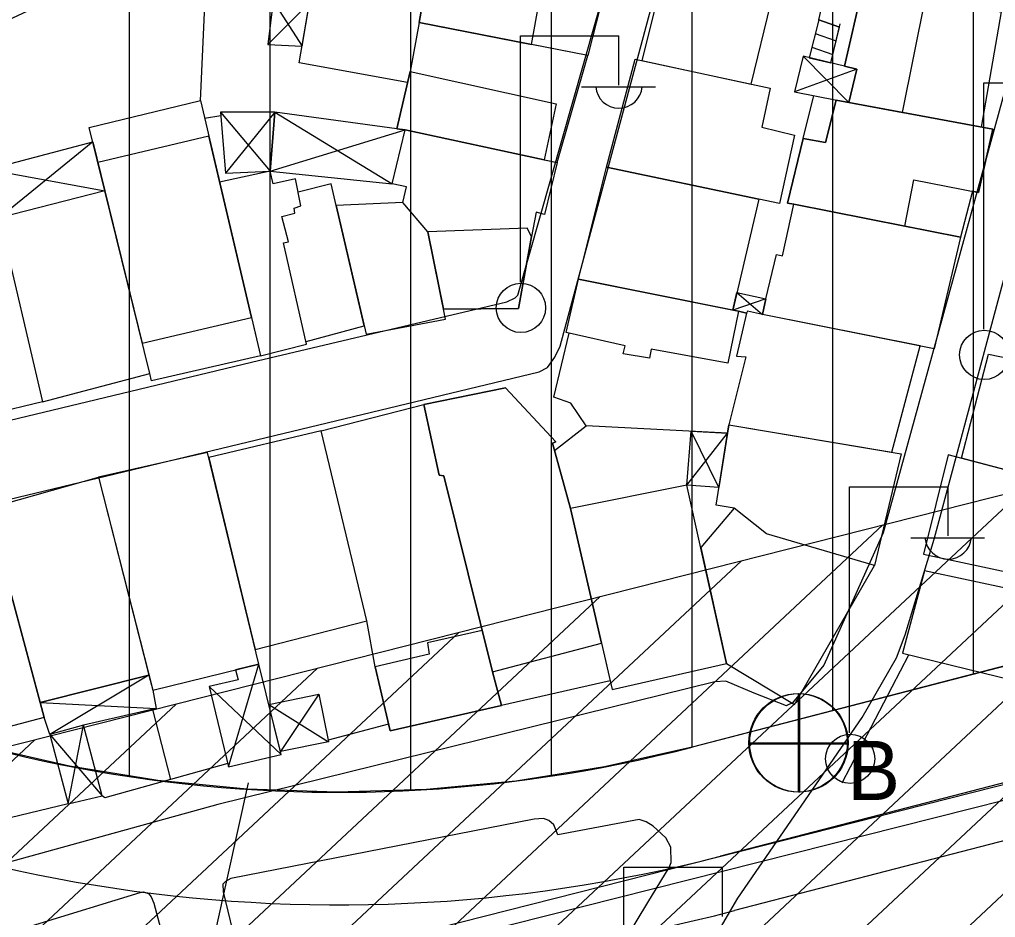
# Model space of a CAD drawing. Extents: x 417997 to 421451, y 4451742 to 4455216.
# Drawn here: x 419463 to 419532.4, y 4452595.7 to 4452659.5 of the extents above; entities that cross this region are included whole.
import ezdxf

# ---------------------------------------------------------------- set-up
doc = ezdxf.new("R2010")
doc.units = 0
for name, color, linetype in [('ADAKENARI', 7, 'Continuous'), ('B_Merdiven', 7, 'Continuous'), ('B_Mesken', 7, 'Continuous'), ('B_Sundurma', 7, 'Continuous'), ('B_Teras', 7, 'Continuous'), ('Hat_ENH', 7, 'Continuous'), ('KALDIRIM', 7, 'Continuous'), ('PL_KON_MEV_350', 7, 'Continuous'), ('S_Elektrik_Diregi', 7, 'Continuous'), ('S_Rogar_Kapagi', 7, 'Continuous'), ('S_Rogar_Kapagi_Buski', 7, 'Continuous'), ('S_Serare', 7, 'Continuous'), ('Sinir_Duvar_tek_tarafa_ait', 7, 'Continuous'), ('Sinir_Ist_Duvari', 7, 'Continuous'), ('TA_ENH_154', 7, 'Continuous'), ('TA_ENH_KORUMA', 7, 'Continuous'), ('TA_ENH_TARAMA', 7, 'Continuous'), ('TR_ORTAYOGUNKONUT', 7, 'Continuous'), ('Yol_Sose', 7, 'Continuous')]:
    doc.layers.add(name, color=color, linetype=linetype)

msp = doc.modelspace()

# ---------------------------------------------------------------- linework, layer by layer
at = {"layer": 'ADAKENARI'}
msp.add_line((419536.19, 4452614.337), (419510.852, 4452607.764), dxfattribs=at)
msp.add_line((419536.19, 4452614.337), (419510.852, 4452607.764), dxfattribs=at)
msp.add_arc((419485.743, 4452704.56), 100, 237.03266, 284.5422, dxfattribs=at)
msp.add_arc((419485.743, 4452704.56), 100, 237.03266, 284.5422, dxfattribs=at)
at = {"layer": 'B_Merdiven'}
for p, q in [((419519.85, 4452659.45), (419521.322, 4452658.932)), ((419519.608, 4452658.475), (419521.086, 4452657.955)), ((419519.366, 4452657.501), (419520.85, 4452656.978))]:
    msp.add_line(p, q, dxfattribs=at)
msp.add_lwpolyline([(419519.85, 4452659.45), (419519.178, 4452656.746), (419520.705, 4452656.377), (419521.322, 4452658.932)], close=True, dxfattribs=at)
at = {"layer": 'B_Mesken'}
for points in [[(419490.633, 4452654.997), (419482.933, 4452656.379), (419483.653, 4452660.642), (419484.79, 4452668.632), (419484.86, 4452669.356), (419492.964, 4452667.865), (419491.446, 4452659.243), (419490.814, 4452655.782)], [(419500.954, 4452666.062), (419505.551, 4452665.187), (419503.447, 4452656.919), (419499.436, 4452657.696), (419491.446, 4452659.243), (419492.99, 4452668.018), (419501.029, 4452666.476)], [(419515.043, 4452654.88), (419516.45, 4452660.606), (419516.928, 4452660.514), (419517.437, 4452662.9), (419509.317, 4452664.699), (419507.285, 4452656.55)], [(419527.417, 4452660.892), (419532.809, 4452660.011), (419531.401, 4452651.824), (419525.8, 4452652.867), (419521.987, 4452653.566), (419522.563, 4452655.929), (419521.677, 4452656.143), (419522.937, 4452661.614)], [(419501.269, 4452649.295), (419503.447, 4452656.919), (419491.446, 4452659.243), (419490.814, 4452655.782), (419489.872, 4452651.709), (419490.461, 4452651.617), (419500.337, 4452649.495)], [(419504.774, 4452648.981), (419506.795, 4452656.656), (419516.403, 4452654.587), (419515.804, 4452651.824), (419518.138, 4452651.251), (419517.056, 4452646.382), (419515.583, 4452646.704)], [(419469.113, 4452647.302), (419467.996, 4452651.783), (419475.9, 4452653.704), (419480.185, 4452635.576), (419472.44, 4452633.791), (419472.302, 4452634.312)], [(419530.792, 4452647.264), (419529.926, 4452643.992), (419525.962, 4452644.783), (419518.093, 4452646.353), (419517.635, 4452646.422), (419518.749, 4452650.999), (419520.34, 4452650.736), (419521.088, 4452653.744), (419532.223, 4452651.672), (419531.21, 4452647.184)], [(419490.285, 4452646.473), (419490.561, 4452647.583), (419489.541, 4452647.79), (419490.461, 4452651.617), (419501.269, 4452649.295), (419500.35, 4452645.604), (419499.761, 4452645.787), (419499.44, 4452644.037), (419498.516, 4452638.941), (419493.187, 4452638.889), (419492.066, 4452644.387)], [(419464.674, 4452632.302), (419443.489, 4452627.183), (419442.095, 4452627.905), (419454.05, 4452647.229), (419459.141, 4452648.35), (419459.79, 4452645.497), (419461.467, 4452645.89), (419461.605, 4452645.371)], [(419483.41, 4452636.588), (419487.555, 4452637.699), (419485.554, 4452646.239), (419485.197, 4452647.781), (419482.852, 4452647.193), (419482.652, 4452648.141), (419481.087, 4452647.783), (419480.863, 4452648.69), (419477.269, 4452647.914), (419479.541, 4452638.301), (419480.185, 4452635.576), (419483.452, 4452636.404)], [(419502.775, 4452641.011), (419504.774, 4452648.981), (419515.583, 4452646.704), (419513.746, 4452638.814)], [(419461.605, 4452645.371), (419464.674, 4452632.302), (419472.302, 4452634.312), (419469.113, 4452647.302)], [(419485.554, 4452646.239), (419487.696, 4452637.097), (419493.335, 4452638.165), (419492.066, 4452644.387), (419490.285, 4452646.473)], [(419528.065, 4452636.077), (419515.844, 4452638.513), (419516.087, 4452639.623), (419516.839, 4452642.766), (419517.269, 4452642.671), (419518.093, 4452646.353), (419529.926, 4452643.992)], [(419513.362, 4452630.077), (419503.324, 4452630.584), (419502.241, 4452632.196), (419501.019, 4452632.63), (419502.11, 4452637.183), (419501.901, 4452637.23), (419502.775, 4452641.011), (419514.149, 4452638.733), (419514.715, 4452638.595), (419514.002, 4452635.54), (419514.682, 4452635.493), (419513.456, 4452630.678)], [(419525.036, 4452628.715), (419527.054, 4452636.279), (419515.844, 4452638.513), (419514.799, 4452638.744), (419514.715, 4452638.595), (419514.002, 4452635.54), (419514.682, 4452635.493), (419513.456, 4452630.678)], [(419529.996, 4452628.297), (419531.915, 4452635.679), (419542.806, 4452633.43), (419541.281, 4452625.856), (419535.799, 4452626.755)], [(419497.312, 4452610.729), (419496.669, 4452613.108), (419493.207, 4452627.05), (419492.884, 4452627.087), (419491.779, 4452632.12), (419497.589, 4452633.3), (419501.164, 4452629.457), (419500.918, 4452629.357), (419502.198, 4452624.723), (419504.402, 4452615.159), (419505.021, 4452612.471)], [(419484.478, 4452630.245), (419491.779, 4452632.12), (419492.884, 4452627.087), (419493.207, 4452627.05), (419495.936, 4452616.059), (419496.669, 4452613.108), (419497.312, 4452610.729), (419489.383, 4452608.926), (419488.316, 4452613.471), (419487.74, 4452616.741)], [(419513.456, 4452630.678), (419525.71, 4452628.601), (419523.826, 4452620.681), (419516.15, 4452622.924), (419513.845, 4452624.743), (419512.554, 4452624.951)], [(419479.804, 4452614.705), (419487.74, 4452616.741), (419484.478, 4452630.245), (419476.508, 4452628.343)], [(419468.658, 4452626.938), (419472.516, 4452611.82), (419480.059, 4452613.65), (419476.42, 4452628.707)], [(419527.289, 4452621.482), (419534.279, 4452619.982), (419535.799, 4452626.755), (419529.063, 4452628.544)], [(419460.837, 4452624.55), (419460.843, 4452624.738), (419468.658, 4452626.938), (419472.244, 4452612.887), (419464.525, 4452610.935)], [(419502.198, 4452624.723), (419505.163, 4452611.854), (419513.289, 4452613.704), (419510.482, 4452626.37)], [(419460.837, 4452624.55), (419464.811, 4452609.877), (419456.962, 4452607.801), (419453.282, 4452622.676)], [(419513.845, 4452624.743), (419511.463, 4452621.941), (419513.289, 4452613.704), (419518.119, 4452610.787), (419523.826, 4452620.681), (419516.15, 4452622.924)], [(419539.107, 4452617.62), (419533.57, 4452618.976), (419527.373, 4452620.289), (419525.809, 4452614.44), (419537.225, 4452611.657), (419537.545, 4452612.451)]]:
    msp.add_lwpolyline(points, close=True, dxfattribs=at)
at = {"layer": 'B_Sundurma'}
for p, q in [((419480.701, 4452657.7), (419483.653, 4452660.642)), ((419481.076, 4452660.768), (419483.133, 4452657.564)), ((419521.987, 4452653.566), (419518.743, 4452656.851)), ((419522.563, 4452655.929), (419518.12, 4452654.328)), ((419477.335, 4452652.884), (419480.863, 4452648.69)), ((419481.184, 4452652.873), (419477.685, 4452648.559)), ((419481.184, 4452652.873), (419489.541, 4452647.79)), ((419480.863, 4452648.69), (419490.461, 4452651.617)), ((419468.25, 4452650.765), (419461.605, 4452645.371)), ((419460.795, 4452648.801), (419469.113, 4452647.302)), ((419514.041, 4452640.078), (419515.844, 4452638.513)), ((419516.087, 4452639.623), (419513.746, 4452638.814)), ((419510.482, 4452626.37), (419513.362, 4452630.077)), ((419512.752, 4452626.21), (419510.784, 4452630.207)), ((419477.905, 4452606.376), (419480.059, 4452613.65)), ((419472.244, 4452612.887), (419465.208, 4452608.676)), ((419476.537, 4452612.086), (419481.638, 4452607.251)), ((419464.525, 4452610.935), (419472.771, 4452610.507)), ((419484.315, 4452611.538), (419481.587, 4452607.459)), ((419480.766, 4452610.785), (419485.018, 4452608.152)), ((419466.512, 4452603.734), (419467.6, 4452609.328)), ((419465.208, 4452608.676), (419468.927, 4452604.318))]:
    msp.add_line(p, q, dxfattribs=at)
for points in [[(419481.076, 4452660.768), (419480.701, 4452657.7), (419483.133, 4452657.564), (419483.653, 4452660.642)], [(419521.987, 4452653.566), (419522.563, 4452655.929), (419518.743, 4452656.851), (419518.12, 4452654.328), (419521.139, 4452653.734)], [(419481.184, 4452652.873), (419477.335, 4452652.884), (419477.685, 4452648.559), (419480.863, 4452648.69)], [(419489.872, 4452651.709), (419481.184, 4452652.873), (419480.863, 4452648.69), (419489.541, 4452647.79), (419490.461, 4452651.617)], [(419460.795, 4452648.801), (419468.25, 4452650.765), (419469.113, 4452647.302), (419461.605, 4452645.371), (419461.467, 4452645.89)], [(419514.041, 4452640.078), (419516.087, 4452639.623), (419515.844, 4452638.513), (419514.799, 4452638.744), (419514.715, 4452638.595), (419514.149, 4452638.733), (419513.746, 4452638.814)], [(419512.752, 4452626.21), (419510.482, 4452626.37), (419510.784, 4452630.207), (419513.362, 4452630.077)], [(419476.537, 4452612.086), (419477.905, 4452606.376), (419481.638, 4452607.251), (419480.059, 4452613.65), (419478.409, 4452613.25), (419478.588, 4452612.544)], [(419464.811, 4452609.877), (419464.525, 4452610.935), (419472.244, 4452612.887), (419472.516, 4452611.82), (419472.771, 4452610.507), (419467.6, 4452609.328), (419465.208, 4452608.676)], [(419480.766, 4452610.785), (419484.315, 4452611.538), (419485.018, 4452608.152), (419481.587, 4452607.459)], [(419465.208, 4452608.676), (419466.512, 4452603.734), (419468.927, 4452604.318), (419467.6, 4452609.328)]]:
    msp.add_lwpolyline(points, close=True, dxfattribs=at)
at = {"layer": 'B_Teras'}
for points in [[(419499.436, 4452657.696), (419501.029, 4452666.476), (419492.99, 4452668.018), (419491.446, 4452659.243)], [(419525.8, 4452652.867), (419527.417, 4452660.892), (419522.937, 4452661.614), (419521.677, 4452656.143), (419522.563, 4452655.929), (419521.987, 4452653.566)], [(419500.337, 4452649.495), (419490.461, 4452651.617), (419489.872, 4452651.709), (419490.814, 4452655.782), (419501.184, 4452653.463)], [(419518.749, 4452650.999), (419517.635, 4452646.422), (419518.093, 4452646.353), (419525.962, 4452644.783), (419526.61, 4452648.064), (419531.21, 4452647.184), (419532.223, 4452651.672), (419521.987, 4452653.566), (419521.088, 4452653.744), (419520.34, 4452650.736)], [(419471.774, 4452636.461), (419479.541, 4452638.301), (419476.496, 4452651.186), (419468.614, 4452649.304), (419469.113, 4452647.302)], [(419480.185, 4452635.576), (419483.452, 4452636.404), (419481.821, 4452643.59), (419482.161, 4452643.657), (419481.691, 4452645.471), (419482.622, 4452645.717), (419482.577, 4452646.057), (419483.054, 4452646.237), (419482.652, 4452648.141), (419481.087, 4452647.783), (419480.863, 4452648.69), (419477.269, 4452647.914), (419479.541, 4452638.301)], [(419493.187, 4452638.889), (419498.516, 4452638.941), (419499.44, 4452644.037), (419499.125, 4452644.649), (419492.066, 4452644.387)], [(419502.775, 4452641.011), (419514.149, 4452638.733), (419513.389, 4452635.043), (419507.95, 4452636.034), (419507.812, 4452635.4), (419505.954, 4452635.722), (419506.092, 4452636.288), (419501.901, 4452637.23)], [(419491.779, 4452632.12), (419492.884, 4452627.087), (419493.207, 4452627.05), (419496.669, 4452613.108), (419504.402, 4452615.159), (419502.198, 4452624.723), (419500.918, 4452629.357), (419501.164, 4452629.457), (419497.589, 4452633.3)], [(419495.936, 4452616.059), (419492.045, 4452615.187), (419492.154, 4452614.373), (419488.316, 4452613.471), (419489.383, 4452608.926), (419497.312, 4452610.729), (419496.669, 4452613.108)]]:
    msp.add_lwpolyline(points, close=True, dxfattribs=at)
at = {"layer": 'Hat_ENH'}
msp.add_lwpolyline([(419643.501, 4452631.847), (419357.517, 4452559.702), (419289.183, 4452591.36)], dxfattribs=at)
at = {"layer": 'KALDIRIM'}
for p, q in [((419674.456, 4452637.806), (419513.865, 4452596.148)), ((419674.456, 4452637.806), (419513.865, 4452596.148)), ((419534.451, 4452605.621), (419512.861, 4452600.02)), ((419534.451, 4452605.621), (419512.861, 4452600.02))]:
    msp.add_line(p, q, dxfattribs=at)
for radius in [108, 108, 112, 112]:
    msp.add_arc((419485.743, 4452704.56), radius, 237.03266, 284.5422, dxfattribs=at)
at = {"layer": 'PL_KON_MEV_350'}
msp.add_lwpolyline([(419567.021, 4452800.801), (419569.824, 4452707.459), (419548.426, 4452626.515), (419536.19, 4452614.337), (419510.852, 4452607.764), (419504.631, 4452606.36), (419498.333, 4452605.356), (419491.984, 4452604.755), (419485.61, 4452604.56), (419479.236, 4452604.772), (419472.889, 4452605.39), (419466.594, 4452606.411), (419460.376, 4452607.831)], dxfattribs=at)
at = {"layer": 'S_Elektrik_Diregi'}
for p, q in [((419498.649, 4452640.811), (419498.649, 4452658.311)), ((419498.649, 4452658.311), (419505.649, 4452658.311)), ((419505.649, 4452654.811), (419505.649, 4452658.311)), ((419502.989, 4452654.671), (419508.239, 4452654.671)), ((419531.582, 4452637.473), (419531.582, 4452654.973)), ((419531.582, 4452654.973), (419538.582, 4452654.973)), ((419522.05, 4452608.772), (419522.05, 4452626.272)), ((419522.05, 4452626.272), (419529.05, 4452626.272)), ((419529.05, 4452622.772), (419529.05, 4452626.272)), ((419526.39, 4452622.632), (419531.64, 4452622.632)), ((419506.01, 4452581.728), (419506.01, 4452599.228)), ((419506.01, 4452599.228), (419513.01, 4452599.228)), ((419513.01, 4452595.728), (419513.01, 4452599.228))]:
    msp.add_line(p, q, dxfattribs=at)
for centre in [(419498.685, 4452638.976), (419531.618, 4452635.637), (419522.086, 4452606.936)]:
    msp.add_circle(centre, 1.75, dxfattribs=at)
for centre in [(419505.65, 4452654.824), (419529.051, 4452622.785)]:
    msp.add_arc(centre, 1.658, 184.83843, 355.14641, dxfattribs=at)
at = {"layer": 'S_Rogar_Kapagi'}
for p, q in [((419518.497, 4452604.543), (419518.497, 4452611.543)), ((419514.927, 4452608.008), (419521.927, 4452608.008))]:
    msp.add_line(p, q, dxfattribs=at)
msp.add_circle((419518.444, 4452608.071), 3.5, dxfattribs=at)
at = {"layer": 'S_Rogar_Kapagi_Buski'}
for p, q in [((419518.383, 4452611.575), (419518.383, 4452604.575)), ((419514.883, 4452608.075), (419521.884, 4452608.075))]:
    msp.add_line(p, q, dxfattribs=at)
msp.add_circle((419518.383, 4452608.075), 3.5, dxfattribs=at)
at = {"layer": 'S_Serare'}
msp.add_lwpolyline([(419479.301, 4452605.222), (419476.265, 4452591.546), (419483.056, 4452593.245), (419480.063, 4452579.688)], dxfattribs=at)
at = {"layer": 'Sinir_Duvar_tek_tarafa_ait'}
for points in [[(419475.9, 4452653.704), (419476.245, 4452661.005)], [(419476.198, 4452652.444), (419477.355, 4452652.638)], [(419501.062, 4452628.835), (419503.324, 4452630.584)], [(419521.511, 4452605.226), (419526.249, 4452614.332)], [(419473.802, 4452605.473), (419472.527, 4452610.451)], [(419489.271, 4452609.403), (419484.993, 4452608.273)], [(419477.852, 4452606.597), (419469.105, 4452604.169), (419468.927, 4452604.318)], [(419466.512, 4452603.734), (419458.244, 4452601.743)]]:
    msp.add_lwpolyline(points, dxfattribs=at)
at = {"layer": 'Sinir_Ist_Duvari'}
for points in [[(419519.85, 4452659.45), (419520.474, 4452662.155), (419522.937, 4452661.614)], [(419520.705, 4452656.377), (419521.374, 4452659.15)], [(419518.749, 4452650.999), (419519.495, 4452654.057)]]:
    msp.add_lwpolyline(points, dxfattribs=at)
at = {"layer": 'TA_ENH_154'}
msp.add_lwpolyline([(421244.229, 4452871.733), (420603.453, 4452866.932), (420104.111, 4452747.147), (419709.07, 4452649.72), (419353.297, 4452559.565), (419284.532, 4452601.288), (419287.681, 4452599.871), (419484.079, 4452691.722), (419833.947, 4454863.938), (419862.826, 4455014.236)], dxfattribs=at)
msp.add_lwpolyline([(421244.229, 4452871.733), (420603.453, 4452866.932), (420104.111, 4452747.147), (419709.07, 4452649.72), (419353.297, 4452559.565), (419284.532, 4452601.288), (419287.681, 4452599.871), (419484.079, 4452691.722), (419833.947, 4454863.938), (419862.826, 4455014.236)], dxfattribs=at)
at = {"layer": 'TA_ENH_KORUMA'}
msp.add_lwpolyline([(419883.153, 4455014.021), (419853.647, 4454860.459), (419502.143, 4452678.088), (419329.549, 4452597.37), (419356.508, 4452581.013), (419704.218, 4452669.124), (420099.383, 4452766.582), (420601.013, 4452886.916), (421244.438, 4452891.737)], dxfattribs=at)
msp.add_lwpolyline([(419883.153, 4455014.021), (419853.647, 4454860.459), (419502.143, 4452678.088), (419329.549, 4452597.37), (419356.508, 4452581.013), (419704.218, 4452669.124), (420099.383, 4452766.582), (420601.013, 4452886.916), (421244.438, 4452891.737)], dxfattribs=at)
at = {"layer": 'TA_ENH_TARAMA'}
for p, q in [((419514.07, 4452579.671), (419574.655, 4452636.292)), ((419514.07, 4452579.671), (419574.655, 4452636.292)), ((419504.022, 4452577.125), (419564.607, 4452633.746)), ((419504.022, 4452577.125), (419564.607, 4452633.746)), ((419493.974, 4452574.579), (419554.559, 4452631.2)), ((419493.974, 4452574.579), (419554.559, 4452631.2)), ((419483.926, 4452572.033), (419544.511, 4452628.654)), ((419483.926, 4452572.033), (419544.511, 4452628.654)), ((419473.878, 4452569.486), (419534.463, 4452626.108)), ((419473.878, 4452569.486), (419534.463, 4452626.108)), ((419463.83, 4452566.94), (419524.415, 4452623.561)), ((419463.83, 4452566.94), (419524.415, 4452623.561)), ((419453.782, 4452564.394), (419514.367, 4452621.015)), ((419453.782, 4452564.394), (419514.367, 4452621.015)), ((419443.734, 4452561.848), (419504.319, 4452618.469)), ((419443.734, 4452561.848), (419504.319, 4452618.469)), ((419433.686, 4452559.302), (419494.271, 4452615.923)), ((419433.686, 4452559.302), (419494.271, 4452615.923)), ((419423.638, 4452556.755), (419484.223, 4452613.377)), ((419423.638, 4452556.755), (419484.223, 4452613.377)), ((419413.59, 4452554.209), (419474.175, 4452610.83)), ((419413.59, 4452554.209), (419474.175, 4452610.83)), ((419403.542, 4452551.663), (419464.127, 4452608.284)), ((419403.542, 4452551.663), (419464.127, 4452608.284))]:
    msp.add_line(p, q, dxfattribs=at)
at = {"layer": 'TR_ORTAYOGUNKONUT'}
for p, q in [((419530.855, 4452612.952), (419530.855, 4452798.319)), ((419530.855, 4452612.952), (419530.855, 4452798.319)), ((419520.855, 4452610.358), (419520.855, 4452707.23)), ((419520.855, 4452610.358), (419520.855, 4452707.23)), ((419510.855, 4452607.764), (419510.855, 4452685.285)), ((419510.855, 4452607.764), (419510.855, 4452685.285)), ((419470.855, 4452605.719), (419470.855, 4452675.784)), ((419470.855, 4452605.719), (419470.855, 4452675.784)), ((419480.855, 4452604.718), (419480.855, 4452673.854)), ((419480.855, 4452604.718), (419480.855, 4452673.854)), ((419490.855, 4452604.72), (419490.855, 4452671.924)), ((419490.855, 4452604.72), (419490.855, 4452671.924)), ((419500.855, 4452605.758), (419500.855, 4452669.994)), ((419500.855, 4452605.758), (419500.855, 4452669.994))]:
    msp.add_line(p, q, dxfattribs=at)
at = {"layer": 'Yol_Sose'}
for points in [[(419441.458, 4452625.972), (419479.527, 4452635.118), (419497.672, 4452639.409), (419498.265, 4452639.68), (419498.471, 4452639.885), (419505.546, 4452664.79), (419505.64, 4452665.45), (419505.527, 4452665.678), (419504.252, 4452666.069), (419486.313, 4452669.017), (419476.75, 4452669.776), (419475.198, 4452669.735), (419472.049, 4452669.288), (419469.446, 4452668.339), (419466.772, 4452666.842), (419464.599, 4452665.253), (419462.107, 4452663.3), (419461.328, 4452662.504), (419454.308, 4452650.466), (419440.817, 4452626.889), (419440.771, 4452626.73), (419440.839, 4452626.433), (419440.952, 4452626.273), (419441.066, 4452626.136)], [(419482.298, 4452580.238), (419498.063, 4452582.257), (419499.066, 4452582.504), (419499.226, 4452582.685), (419507.698, 4452596.721), (419509.232, 4452599.219), (419509.37, 4452599.56), (419509.328, 4452600.652), (419508.989, 4452601.313), (419508.081, 4452602.158), (419507.581, 4452602.456), (419507.08, 4452602.617), (419501.315, 4452601.543), (419501.022, 4452602.25), (419500.658, 4452602.547), (419500.294, 4452602.685), (419499.634, 4452602.641), (419478.077, 4452598.434), (419477.69, 4452598.23), (419477.507, 4452598.026), (419477.528, 4452597.48), (419481.481, 4452581.105), (419481.775, 4452580.558)], [(419472.595, 4452596.689), (419474.961, 4452587.797), (419439.311, 4452578.927), (419438.778, 4452579.044), (419438.286, 4452579.828), (419438.085, 4452580.527), (419437.936, 4452581.064), (419437.789, 4452581.762), (419437.769, 4452582.137), (419437.986, 4452583.629), (419438.055, 4452584.43), (419438.255, 4452585.068), (419438.644, 4452585.809), (419439.083, 4452586.362), (419439.733, 4452586.751), (419443.24, 4452588.235), (419464.218, 4452595.163), (419471.62, 4452597.429), (419471.862, 4452597.478), (419472.207, 4452597.364), (419472.416, 4452597.12)]]:
    msp.add_lwpolyline(points, close=True, dxfattribs=at)
for points in [[(419413.985, 4452613.767), (419499.982, 4452634.428), (419500.576, 4452634.746), (419501.102, 4452635.473), (419501.47, 4452636.247), (419509.088, 4452664.545), (419509.386, 4452665.022), (419509.683, 4452665.135), (419533.997, 4452660.616), (419534.43, 4452660.433), (419534.611, 4452659.999), (419524.432, 4452622.982), (419520.206, 4452613.585), (419517.985, 4452610.926), (419517.642, 4452610.745), (419517.551, 4452610.7), (419515.251, 4452611.596), (419513.247, 4452612.445), (419512.472, 4452612.402), (419477.147, 4452603.694), (419458.843, 4452598.647)], [(419499.017, 4452517.864), (419503.321, 4452566.529), (419504.444, 4452575.131), (419505.925, 4452582.162), (419507.28, 4452585.368), (419514.109, 4452597.025), (419522.949, 4452609.865), (419525.379, 4452614.116), (419526, 4452615.754), (419528.051, 4452622.534), (419533.659, 4452643.378), (419538.023, 4452659.567), (419538.343, 4452659.885), (419538.685, 4452659.884), (419561.039, 4452655.054), (419561.653, 4452654.551), (419561.879, 4452653.707), (419552.58, 4452620.705), (419548.299, 4452608.214), (419542.158, 4452592.016), (419528.451, 4452556.185), (419528.036, 4452554.843), (419527.871, 4452553.181)]]:
    msp.add_lwpolyline(points, dxfattribs=at)

# ---------------------------------------------------------------- texts
at = {"layer": 'S_Rogar_Kapagi_Buski'}
msp.add_text('B', height=4.2, dxfattribs=at).set_placement((419521.884, 4452604.011))

doc.saveas('drawing.dxf')
